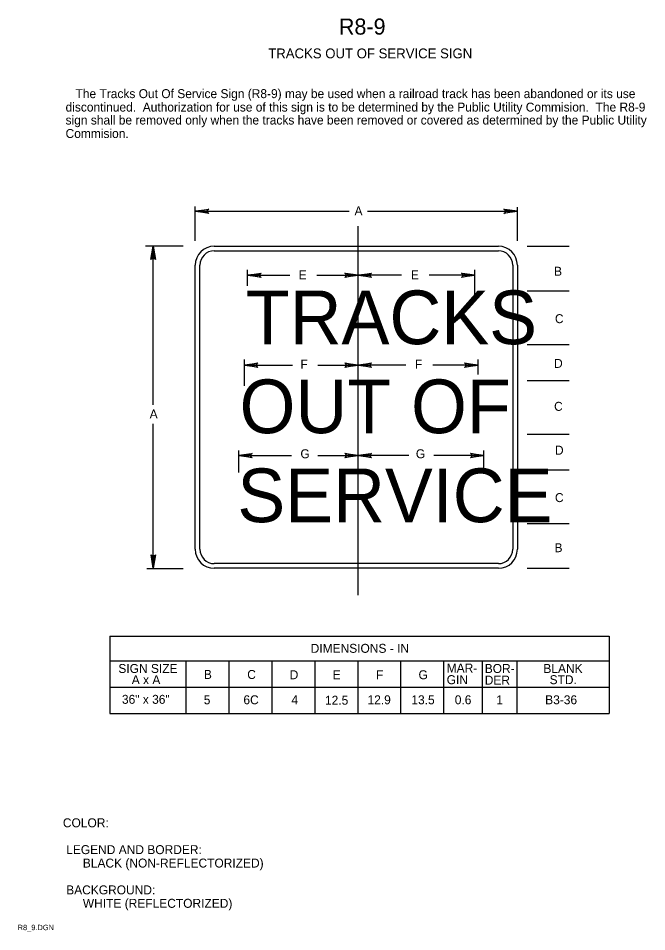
# Model space of a CAD drawing. Extents: x 0.013 to 0.188, y 0.004 to 0.259.
import ezdxf

# ---------------------------------------------------------------- set-up
doc = ezdxf.new("R2010")
doc.units = 0
for name, color, linetype in [('1', 7, 'Continuous'), ('3', 7, 'Continuous'), ('5', 7, 'Continuous')]:
    doc.layers.add(name, color=color, linetype=linetype)

# ---------------------------------------------------------------- blocks, each defined once
blk = doc.blocks.new('RARROW')
at = {"layer": '3'}
for p, q in [((-2.156, 0.285), (-2.2665, 0.384625)), ((-2.2665, 0.384625), (0, 0)), ((0, 0), (-2.2665, -0.379125)), ((-2.156, 0.285), (-2.075625, 0.12075)), ((0, 0), (-2.156, 0.285)), ((-2.14975, -0.2705), (0, 0)), ((-2.075625, 0.12075), (0, 0)), ((0, 0), (-2.074, -0.108)), ((-2.2665, -0.379125), (-2.14975, -0.2705)), ((-2.074, -0.108), (-2.14975, -0.2705))]:
    blk.add_line(p, q, dxfattribs=at)

msp = doc.modelspace()

# ---------------------------------------------------------------- linework, layer by layer
at = {"layer": '3'}
for p, q in [((0.06742, 0.1942), (0.14682, 0.1942)), ((0.06343, 0.11113), (0.06343, 0.1902)), ((0.15082, 0.1902), (0.15082, 0.1108)), ((0.06343, 0.1108), (0.06343, 0.11113)), ((0.14682, 0.1068), (0.06742, 0.1068)), ((0.03825, 0.0865), (0.17775, 0.0865)), ((0.03825, 0.0865), (0.03825, 0.06488)), ((0.17775, 0.0865), (0.17775, 0.06488)), ((0.03825, 0.07963), (0.17775, 0.07963)), ((0.0595, 0.07963), (0.0595, 0.06488)), ((0.0715, 0.07963), (0.0715, 0.06488)), ((0.0835, 0.07963), (0.0835, 0.06488)), ((0.0955, 0.07963), (0.0955, 0.06488)), ((0.1075, 0.07963), (0.1075, 0.06488)), ((0.1195, 0.07963), (0.1195, 0.06488)), ((0.1315, 0.07963), (0.1315, 0.06488)), ((0.14225, 0.07963), (0.14225, 0.06488)), ((0.152, 0.07963), (0.152, 0.06488)), ((0.03825, 0.07225), (0.17775, 0.07225)), ((0.03825, 0.06488), (0.17775, 0.06488))]:
    msp.add_line(p, q, dxfattribs=at)
for centre, start, end in [((0.06742, 0.1902), 90, 180), ((0.14682, 0.1902), 0, 90), ((0.06742, 0.1108), 180, 270), ((0.14682, 0.1108), 270, 0)]:
    msp.add_arc(centre, 0.004, start, end, dxfattribs=at)
at = {"layer": '5'}
for p, q in [((0.06212, 0.197), (0.06212, 0.20663)), ((0.06212, 0.20525), (0.10512, 0.20525)), ((0.11025, 0.20525), (0.15213, 0.20525)), ((0.15213, 0.197), (0.15213, 0.20638)), ((0.10762, 0.098), (0.10762, 0.20112)), ((0.05875, 0.1955), (0.04825, 0.1955)), ((0.05038, 0.15113), (0.05038, 0.1955)), ((0.06742, 0.1955), (0.14682, 0.1955)), ((0.15488, 0.1955), (0.16662, 0.1955)), ((0.06212, 0.11113), (0.06212, 0.1902)), ((0.15213, 0.1902), (0.15213, 0.1108)), ((0.07675, 0.18438), (0.07675, 0.18888)), ((0.07675, 0.18738), (0.0885, 0.18738)), ((0.09613, 0.18738), (0.10762, 0.18738)), ((0.11975, 0.18738), (0.10762, 0.18738)), ((0.14025, 0.18738), (0.1275, 0.18738)), ((0.14025, 0.182), (0.14025, 0.18888)), ((0.15488, 0.183), (0.16662, 0.183)), ((0.15488, 0.168), (0.16662, 0.168)), ((0.07587, 0.1565), (0.07587, 0.16387)), ((0.14113, 0.15963), (0.14113, 0.16387)), ((0.07587, 0.16225), (0.08925, 0.16225)), ((0.09638, 0.16225), (0.10762, 0.16225)), ((0.121, 0.16225), (0.10762, 0.16225)), ((0.14113, 0.16225), (0.1285, 0.16225)), ((0.15488, 0.158), (0.16662, 0.158)), ((0.05038, 0.1055), (0.05038, 0.14588)), ((0.15488, 0.143), (0.16662, 0.143)), ((0.07425, 0.13225), (0.07425, 0.13837)), ((0.14275, 0.13337), (0.14275, 0.13837)), ((0.07425, 0.137), (0.089, 0.137)), ((0.09638, 0.137), (0.10762, 0.137)), ((0.12175, 0.137), (0.10762, 0.137)), ((0.14275, 0.137), (0.12875, 0.137)), ((0.15488, 0.133), (0.16662, 0.133)), ((0.15488, 0.118), (0.16662, 0.118)), ((0.06212, 0.1108), (0.06212, 0.11113)), ((0.05875, 0.10537), (0.04863, 0.10537)), ((0.14682, 0.1055), (0.06742, 0.1055)), ((0.15488, 0.1055), (0.16662, 0.1055))]:
    msp.add_line(p, q, dxfattribs=at)
for centre, start, end in [((0.06742, 0.1902), 90, 180), ((0.14682, 0.1902), 0, 90), ((0.06742, 0.1108), 180, 270), ((0.14682, 0.1108), 270, 0)]:
    msp.add_arc(centre, 0.0053, start, end, dxfattribs=at)

# ---------------------------------------------------------------- block references
at = {"layer": '3', "xscale": 0.0016545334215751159, "yscale": 0.0016366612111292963}
for p, rotation in [((0.06212, 0.20525), 180), ((0.05038, 0.1955), 90), ((0.07675, 0.18738), 180), ((0.10762, 0.18738), 180), ((0.07587, 0.16225), 180), ((0.10762, 0.16225), 180), ((0.07425, 0.137), 180), ((0.10762, 0.137), 180), ((0.05038, 0.1055), -90)]:
    msp.add_blockref('RARROW', p, dxfattribs=dict(at, rotation=rotation))
for p in [(0.15213, 0.20525), (0.10762, 0.18738), (0.14025, 0.18738), (0.10762, 0.16225), (0.14113, 0.16225), (0.10762, 0.137), (0.14275, 0.137)]:
    msp.add_blockref('RARROW', p, dxfattribs=at)

# ---------------------------------------------------------------- texts
at = {"layer": '1'}
for s, height, p in [('R8-9', 0.0045, (0.10225, 0.25462)), ('TRACKS OUT OF SERVICE SIGN', 0.0027503, (0.0825, 0.248)), ('TRACKS', 0.015, (0.07625, 0.16812)), ('OUT OF', 0.015, (0.0745, 0.14325)), ('SERVICE', 0.015, (0.07387, 0.11838)), ('COLOR:', 0.0025, (0.02513, 0.03313)), (' LEGEND AND BORDER:', 0.0024998, (0.02513, 0.02563)), ('      BLACK (NON-REFLECTORIZED)', 0.0024998, (0.02513, 0.02188)), (' BACKGROUND:', 0.0024998, (0.02513, 0.01438)), ('      WHITE (REFLECTORIZED)', 0.0024998, (0.02513, 0.01063)), ('R8_9.DGN', 0.0015, (0.0125, 0.00438))]:
    msp.add_text(s, height=height, dxfattribs=at).set_placement(p)
at = {"layer": '3'}
for s, height, p in [('   The Tracks Out Of Service Sign (R8-9) may be used when a railroad track has been abandoned or its use', 0.00249975, (0.02588, 0.23688)), ('discontinued.  Authorization for use of this sign is to be determined by the Public Utility Commision.  The R8-9', 0.00249975, (0.02588, 0.23312)), ('sign shall be removed only when the tracks have been removed or covered as determined by the Public Utility', 0.00249975, (0.02588, 0.2295)), ('Commision.  ', 0.0024998, (0.02588, 0.22575)), ('DIMENSIONS - IN', 0.0024998, (0.09436, 0.08188)), ('SIGN SIZE', 0.0025, (0.04063, 0.07625)), ('B', 0.0025, (0.06452, 0.07458)), ('C', 0.0025, (0.07664, 0.07458)), ('D', 0.0025, (0.0885, 0.0745)), ('E', 0.0025, (0.1005, 0.0745)), ('F', 0.0025, (0.11263, 0.0745)), ('G', 0.0025, (0.1245, 0.0745)), ('MAR-', 0.0025, (0.13237, 0.07637)), ('BOR-', 0.0025, (0.143, 0.07625)), ('BLANK', 0.0025, (0.15938, 0.07625)), ('A x A', 0.0025, (0.04437, 0.07312)), ('GIN', 0.0025, (0.13237, 0.07312)), ('DER', 0.0025, (0.143, 0.073)), ('STD.', 0.0025, (0.16112, 0.07312)), ('36" x 36"', 0.0025, (0.04163, 0.06763)), ('5', 0.0025, (0.06449, 0.0675)), ('6C', 0.0025, (0.07557, 0.0675)), ('4', 0.0025, (0.08897, 0.0675)), ('12.5', 0.0025, (0.09837, 0.06738)), ('12.9', 0.0025, (0.11025, 0.0675)), ('13.5', 0.0025, (0.1225, 0.0675)), ('0.6', 0.0025, (0.13463, 0.0675)), ('1', 0.0025, (0.14624, 0.0675)), ('B3-36', 0.0025, (0.15989, 0.0675))]:
    msp.add_text(s, height=height, dxfattribs=at).set_placement(p)
at = {"layer": '5'}
for s, p in [('A', (0.10662, 0.20413)), ('B', (0.16237, 0.18725)), ('E', (0.091, 0.18625)), ('E', (0.12237, 0.18625)), ('C', (0.16262, 0.174)), ('F', (0.0915, 0.16125)), ('F', (0.1235, 0.16125)), ('D', (0.16237, 0.1615)), ('C', (0.16237, 0.1495)), ('A', (0.04938, 0.14738)), ('G', (0.0915, 0.13625)), ('G', (0.12375, 0.13625)), ('D', (0.16262, 0.13725)), ('C', (0.16262, 0.124)), ('B', (0.1625, 0.11))]:
    msp.add_text(s, height=0.0025, dxfattribs=at).set_placement(p)

doc.saveas('drawing.dxf')
